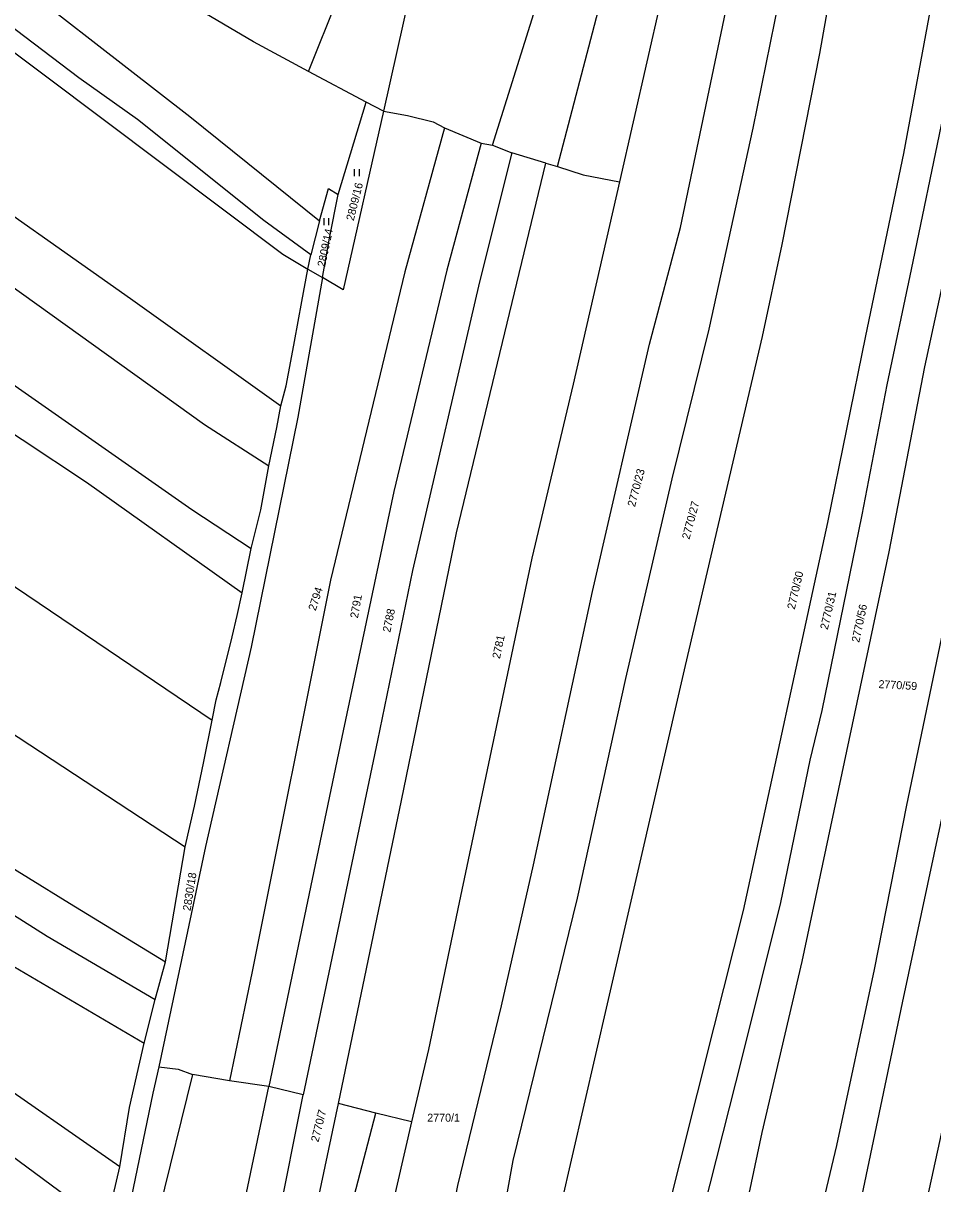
# Model space of a CAD drawing. Extents: x -755528 to -748832, y -1118122 to -1111095.
# Drawn here: x -753827.4 to -753634.1, y -1114826.1 to -1114579.5 of the extents above; entities that cross this region are included whole.
import ezdxf

# ---------------------------------------------------------------- set-up
doc = ezdxf.new("R2010")
doc.units = 0
for name, color, linetype in [('DZ_DO_PUPFL', 7, 'Continuous'), ('DZ_NAD_ZPF', 7, 'Continuous'), ('TZ_UMVŽST', 7, 'Continuous')]:
    doc.layers.add(name, color=color, linetype=linetype)

msp = doc.modelspace()

# ---------------------------------------------------------------- linework, layer by layer
at = {"layer": 'DZ_NAD_ZPF'}
for p, q in [((-753766.81, -1114589.78), (-753755.1, -1114560.7)), ((-753754.52, -1114596.32), (-753766.81, -1114589.78)), ((-753760.46, -1114615.92), (-753754.52, -1114596.32)), ((-753750.88, -1114598.22), (-753754.52, -1114596.32)), ((-753737.87, -1114601.71), (-753730.09, -1114604.97)), ((-753730.09, -1114604.97), (-753727.69, -1114605.4)), ((-753727.69, -1114605.4), (-753723.57, -1114607.04)), ((-753716.34, -1114609.22), (-753723.57, -1114607.04)), ((-753716.34, -1114609.22), (-753713.89, -1114609.93)), ((-753764.44, -1114621.51), (-753766.3, -1114628.7)), ((-753766.93, -1114631.73), (-753766.3, -1114628.7)), ((-753766.93, -1114631.73), (-753763.81, -1114633.56)), ((-753780.9, -1114700.52), (-753779.01, -1114691.09)), ((-753797.22, -1114778.89), (-753793.03, -1114754.47)), ((-753799.4, -1114786.94), (-753797.22, -1114778.89)), ((-753801.69, -1114796.2), (-753799.4, -1114786.94)), ((-753783.6, -1114804.21), (-753791.42, -1114802.85)), ((-753775.22, -1114805.4), (-753783.6, -1114804.21)), ((-753767.91, -1114807.15), (-753775.22, -1114805.4)), ((-753752.47, -1114811.02), (-753760.42, -1114808.97)), ((-753744.88, -1114812.91), (-753752.47, -1114811.02)), ((-753809.79, -1114834.95), (-753806.92, -1114822.44))]:
    msp.add_line(p, q, dxfattribs=at)
for points in [[(-753727.69, -1114605.4), (-753712.79, -1114557.95), (-753700.95, -1114511.18), (-753692.02, -1114479.35)], [(-753713.89, -1114609.93), (-753702.49, -1114566.31), (-753691.72, -1114520.85), (-753682.69, -1114486.12)], [(-753973.67, -1114489.15), (-753929.61, -1114507.83), (-753905.65, -1114518.9), (-753879.04, -1114533.76), (-753839.34, -1114562.55), (-753792.02, -1114599.36), (-753764.44, -1114621.51)], [(-753766.3, -1114628.7), (-753776.29, -1114621.4), (-753803.14, -1114599.97), (-753815.6, -1114591.13), (-753834.8, -1114576.63), (-753871.73, -1114550.25), (-753883.91, -1114541.75), (-753905.54, -1114528.64), (-753932.39, -1114515.25), (-753951.79, -1114506.5), (-753963.41, -1114501.89), (-753978.14, -1114494.33)], [(-753980.54, -1114497.11), (-753964.46, -1114503.37), (-753927.91, -1114519.59), (-753886.84, -1114542.44), (-753772.24, -1114628.6), (-753766.93, -1114631.73)], [(-753675.18, -1114495.05), (-753689.07, -1114562.16), (-753700.67, -1114613.23)], [(-754005.15, -1114507.68), (-753982.58, -1114519.79), (-753964.03, -1114528.47), (-753930.12, -1114547.54), (-753900.4, -1114567.21), (-753881.25, -1114582.51), (-753844.84, -1114609.65), (-753804.64, -1114638.01), (-753772.64, -1114660.8)], [(-753794.59, -1115077.61), (-753787.93, -1115060.8), (-753777.91, -1115023.56), (-753764.5, -1114964.39), (-753747.45, -1114890.29), (-753735.04, -1114826.44), (-753725.78, -1114788.24), (-753719.01, -1114758.28), (-753706.47, -1114700.23), (-753694.32, -1114647.7), (-753687.72, -1114622.89), (-753664.72, -1114512.91)], [(-754016.44, -1114515.73), (-754009.95, -1114516.85), (-753991, -1114525.89), (-753973.33, -1114534.46), (-753943.34, -1114553.41), (-753912.75, -1114574.24), (-753860.27, -1114613.62), (-753788.9, -1114664.79), (-753775.21, -1114673.56)], [(-753748.31, -1114942.85), (-753742.18, -1114916.5), (-753736.38, -1114892.22), (-753730.62, -1114858.93), (-753728.07, -1114844.73), (-753724.64, -1114828.54), (-753723.28, -1114821.11), (-753709.62, -1114765.41), (-753699.36, -1114718.72), (-753689.49, -1114676.33), (-753681.62, -1114644.48), (-753672.27, -1114601.8), (-753665.84, -1114570.01), (-753657.14, -1114527.54)], [(-754035.11, -1114531.65), (-754017.95, -1114532.83), (-754004.05, -1114536.71), (-753985.75, -1114545.16), (-753967.67, -1114556.02), (-753946.4, -1114571.84), (-753923.61, -1114589.45), (-753869.1, -1114629.88), (-753829.86, -1114656.07), (-753791.6, -1114682.84), (-753779.01, -1114691.09)], [(-754041.64, -1114536.87), (-754022.57, -1114540.88), (-754006.04, -1114547.32), (-753991.81, -1114554.8), (-753971.54, -1114567.51), (-753943.82, -1114587.27), (-753924.84, -1114601.57), (-753895.28, -1114622.53), (-753841.37, -1114658.87), (-753813.99, -1114676.99), (-753780.9, -1114700.52)], [(-753719.31, -1114858.54), (-753713.16, -1114830.85), (-753703.28, -1114787.85), (-753686.64, -1114715.99), (-753670.27, -1114646.05), (-753666.14, -1114626.53), (-753658.11, -1114585.95), (-753650.23, -1114541.59)], [(-753755.1, -1114560.7), (-753743.81, -1114566.78), (-753750.88, -1114598.22)], [(-753696.84, -1114855.73), (-753691.24, -1114835.28), (-753680.55, -1114792.69), (-753674.32, -1114768), (-753656.4, -1114685.57), (-753648.33, -1114645.93), (-753640.26, -1114607.21), (-753633.95, -1114573.16)], [(-753766.81, -1114589.78), (-753778.48, -1114583.49), (-753791.23, -1114575.97)], [(-754006.04, -1114580.49), (-753960.65, -1114610.89), (-753930.04, -1114632.09), (-753897.65, -1114653.96), (-753861.39, -1114678.36), (-753831.44, -1114697.72), (-753787.25, -1114727.57)], [(-753692.5, -1114869), (-753689.97, -1114860.37), (-753684.09, -1114836.72), (-753674.61, -1114799.31), (-753666.41, -1114766.32), (-753660.14, -1114736.05), (-753657.6, -1114725.49), (-753649.09, -1114683.97), (-753643.82, -1114656.31), (-753638.66, -1114631.83), (-753631.88, -1114599.38), (-753628.52, -1114582.03)], [(-753682.77, -1114871.3), (-753676.87, -1114845.91), (-753670.36, -1114815.19), (-753661.87, -1114778.82), (-753643.37, -1114691.82), (-753635.78, -1114652.49), (-753628.1, -1114616.86), (-753622.99, -1114590.06)], [(-753750.88, -1114598.22), (-753759.4, -1114636.12), (-753763.81, -1114633.56)], [(-753750.88, -1114598.22), (-753745.76, -1114599.11), (-753740.33, -1114600.47), (-753737.87, -1114601.71)], [(-753737.87, -1114601.71), (-753746.31, -1114632.36), (-753762.13, -1114697.8), (-753778.74, -1114780.93), (-753783.6, -1114804.21)], [(-753730.09, -1114604.97), (-753737.42, -1114631.99), (-753748.67, -1114678.99), (-753759.45, -1114729.81), (-753775.22, -1114805.4)], [(-753723.57, -1114607.04), (-753730.47, -1114634.47), (-753744.71, -1114695.74), (-753752.12, -1114731.9), (-753767.91, -1114807.15)], [(-753610.25, -1114606.01), (-753617.12, -1114637.26), (-753624.49, -1114671.37), (-753632.34, -1114710.29), (-753639.7, -1114745.63), (-753646.59, -1114780.5), (-753654.58, -1114817.91), (-753663.71, -1114856.29), (-753671.41, -1114887.98), (-753679.86, -1114921.84)], [(-754012.15, -1114608.47), (-753988.26, -1114624.88), (-753972.82, -1114636.12), (-753919.58, -1114671.95), (-753873.88, -1114701.73), (-753830.77, -1114729.66), (-753793.03, -1114754.47)], [(-753760.42, -1114808.97), (-753747.05, -1114744.66), (-753735.34, -1114687.76), (-753716.34, -1114609.22)], [(-753713.89, -1114609.93), (-753708.41, -1114611.73), (-753700.67, -1114613.23)], [(-753764.44, -1114621.51), (-753762.55, -1114614.62), (-753760.46, -1114615.92)], [(-753700.67, -1114613.23), (-753710.56, -1114656.17), (-753719.31, -1114693.13), (-753734.77, -1114766.3), (-753741.27, -1114797.56), (-753744.88, -1114812.91)], [(-753604.79, -1114614.61), (-753613.99, -1114658.59), (-753629.87, -1114737.18), (-753640.64, -1114787.58), (-753650.44, -1114834.53), (-753663.46, -1114889.5), (-753671.97, -1114923.35)], [(-753763.81, -1114633.56), (-753762.31, -1114625.18), (-753760.46, -1114615.92)], [(-753772.64, -1114660.8), (-753771.56, -1114656.55), (-753770.53, -1114651.29), (-753769.79, -1114647.15), (-753768.23, -1114638.62), (-753766.93, -1114631.73)], [(-754018.86, -1114633.9), (-753991.84, -1114651.56), (-753944.26, -1114684.67), (-753891.31, -1114720.08), (-753878.77, -1114728.45), (-753843.79, -1114750.33), (-753817.6, -1114766.43), (-753797.22, -1114778.89)], [(-753763.81, -1114633.56), (-753769.08, -1114663.2), (-753779, -1114712.04), (-753788.65, -1114754.43), (-753798.57, -1114801.23)], [(-753592.96, -1114636.98), (-753601.26, -1114669.82), (-753605.55, -1114692.31), (-753616.04, -1114739.83), (-753628.68, -1114798.6), (-753643.43, -1114866.36)], [(-754020.76, -1114642.73), (-753997.37, -1114658.12), (-753944.57, -1114694.55), (-753889.95, -1114731.89), (-753846.8, -1114758.03), (-753822.32, -1114773.42), (-753799.4, -1114786.94)], [(-754022.72, -1114650.6), (-753994.83, -1114669.44), (-753950.22, -1114701.08), (-753917.06, -1114724.81), (-753896.72, -1114739.61), (-753846.36, -1114769.99), (-753801.69, -1114796.2)], [(-753775.21, -1114673.56), (-753773.55, -1114665.4), (-753772.64, -1114660.8)], [(-753806.92, -1114822.44), (-753836.67, -1114801.81), (-753872.53, -1114777.48), (-753895.08, -1114763.26), (-753910.75, -1114754.73), (-753919.85, -1114741.17), (-753920.09, -1114740.22), (-753930, -1114733.83), (-753931.58, -1114732.41), (-753990.09, -1114692.21), (-754027.62, -1114666.84)], [(-753779.01, -1114691.09), (-753776.94, -1114682.9), (-753775.21, -1114673.56)], [(-753787.25, -1114727.57), (-753786.4, -1114723.28), (-753785.43, -1114719.56), (-753783.05, -1114709.89), (-753781.97, -1114705.36), (-753780.9, -1114700.52)], [(-753793.03, -1114754.47), (-753791.04, -1114745.82), (-753789.09, -1114736.68), (-753787.25, -1114727.57)], [(-753809.79, -1114834.95), (-753856.88, -1114800.2), (-753890.97, -1114776.38), (-753909.62, -1114763.9)], [(-753806.92, -1114822.44), (-753804.84, -1114809.87), (-753801.69, -1114796.2)], [(-753791.42, -1114802.85), (-753798.62, -1114831.84), (-753806.47, -1114870.47), (-753828.68, -1114969.47), (-753835.5, -1115004.32), (-753839.23, -1115017.91)], [(-753798.57, -1114801.23), (-753799.91, -1114806.81), (-753814.84, -1114878.99)], [(-753798.57, -1114801.23), (-753794.52, -1114801.72), (-753791.42, -1114802.85)], [(-753827.22, -1115042.47), (-753824.75, -1115029.79), (-753815.18, -1114985.65), (-753800.65, -1114920.02), (-753786.23, -1114857.67), (-753775.22, -1114805.4)], [(-753821.74, -1115050.21), (-753812.98, -1115010.4), (-753802.75, -1114964.66), (-753791.79, -1114915.39), (-753783.28, -1114877.36), (-753773.41, -1114834.52), (-753767.91, -1114807.15)], [(-753815.75, -1115057.27), (-753812.74, -1115047.08), (-753811.02, -1115038.9), (-753800.47, -1114993.4), (-753793.97, -1114963.65), (-753778.1, -1114891.75), (-753767.92, -1114844.45), (-753760.42, -1114808.97)], [(-753810.37, -1115062.57), (-753804.42, -1115042.36), (-753797.25, -1115010.97), (-753786.03, -1114958.91), (-753770.33, -1114887.7), (-753757.09, -1114828.71), (-753752.47, -1114811.02)], [(-753744.88, -1114812.91), (-753755.85, -1114860.59), (-753768.37, -1114915.99), (-753784.17, -1114987.23), (-753793.11, -1115028.22), (-753799.33, -1115052.95), (-753804.69, -1115068.16)]]:
    msp.add_lwpolyline(points, dxfattribs=at)
at = {"layer": 'TZ_UMVŽST'}
for p, q in [((-753756.991, -1114612.04), (-753756.991, -1114610.54)), ((-753755.99, -1114612.04), (-753755.99, -1114610.54)), ((-753763.491, -1114622.44), (-753763.491, -1114620.94)), ((-753762.49, -1114622.44), (-753762.49, -1114620.94))]:
    msp.add_line(p, q, dxfattribs=at)

# ---------------------------------------------------------------- texts
at = {"layer": 'DZ_DO_PUPFL'}
for s, rotation, p in [('2809/16', 76, (-753757.185, -1114621.595)), ('2809/14', 78, (-753763.288, -1114631.406)), ('2770/23', 75, (-753697.418, -1114682.369)), ('2770/27', 75, (-753685.838, -1114689.269)), ('2770/30', 77, (-753663.451, -1114704.151)), ('2794', 72, (-753765.281, -1114704.452)), ('2791', 80, (-753756.302, -1114706.017)), ('2770/31', 77, (-753656.441, -1114708.451)), ('2788', 78, (-753749.418, -1114709.026)), ('2770/56', 78, (-753649.748, -1114711.166)), ('2781', 78, (-753726.118, -1114714.626)), ('2770/59', 357, (-753645.694, -1114720.748)), ('2830/18', 81, (-753791.87, -1114768.182)), ('2770/7', 76, (-753764.675, -1114817.305))]:
    msp.add_text(s, height=1.7, rotation=rotation, dxfattribs=at).set_placement(p)
msp.add_text('2770/1', height=1.7, dxfattribs=at).set_placement((-753741.56, -1114812.86))

doc.saveas('drawing.dxf')
